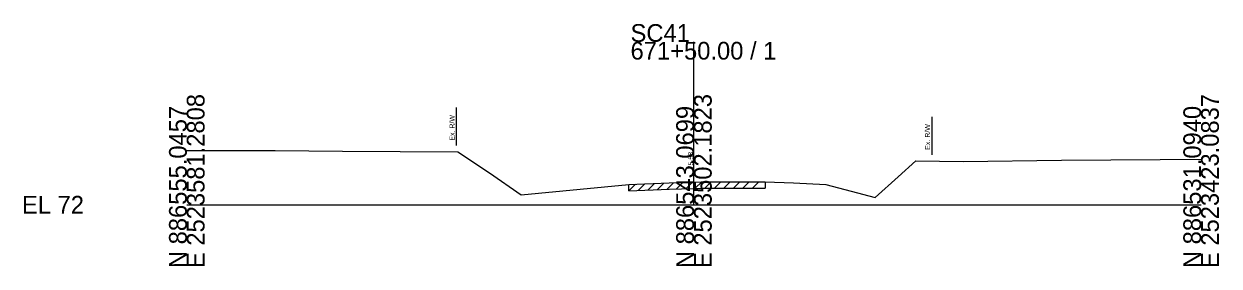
# Model space of a CAD drawing. Extents: x -26 to 183, y -10 to 24021.
# Drawn here: x -25.7 to 162.8, y 3990.3 to 4028.6 of the extents above; entities that cross this region are included whole.
import ezdxf

# ---------------------------------------------------------------- set-up
doc = ezdxf.new("R2010")
doc.units = 0
for name, color, linetype in [('RD_GPK_XS_Cell', 7, 'Continuous'), ('RD_XS_ExGround', 7, 'Continuous'), ('RD_XS_ExPaveRet', 7, 'Continuous'), ('RD_XS_ExRW', 7, 'Continuous'), ('RD_XS_TX_Elev_EX', 7, 'Continuous')]:
    doc.layers.add(name, color=color, linetype=linetype)

msp = doc.modelspace()

# ---------------------------------------------------------------- linework, layer by layer
at = {"layer": 'RD_GPK_XS_Cell'}
for p, q in [((80, 4000), (80, 4025.72)), ((0, 4000), (80, 4000)), ((80, 4000), (160, 4000))]:
    msp.add_line(p, q, dxfattribs=at)
at = {"layer": 'RD_XS_ExGround'}
for p, q in [((0, 4008.56), (2.23, 4008.57)), ((2.23, 4008.57), (13.92, 4008.56)), ((13.92, 4008.56), (24.55, 4008.48)), ((24.55, 4008.48), (42.76, 4008.33)), ((42.76, 4008.33), (47.75, 4005.03)), ((112.24, 4004.42), (115.01, 4006.93)), ((115.01, 4006.93), (122.48, 4006.83)), ((122.48, 4006.83), (138, 4007.06)), ((138, 4007.06), (153.56, 4007.15)), ((153.56, 4007.15), (160, 4007.18)), ((47.75, 4005.03), (52.77, 4001.55)), ((62.05, 4002.44), (69.72, 4003.21)), ((69.72, 4003.21), (76.1, 4003.44)), ((76.1, 4003.44), (80, 4003.58)), ((80, 4003.58), (81.14, 4003.62)), ((81.14, 4003.62), (85.47, 4003.62)), ((85.47, 4003.62), (91.26, 4003.63)), ((91.26, 4003.63), (95.7, 4003.44)), ((95.7, 4003.44), (100.8, 4003.19)), ((100.8, 4003.19), (104.78, 4002.15)), ((108.57, 4001.14), (112.24, 4004.42)), ((52.77, 4001.55), (62.05, 4002.44)), ((104.78, 4002.15), (108.57, 4001.14))]:
    msp.add_line(p, q, dxfattribs=at)
at = {"layer": 'RD_XS_ExPaveRet'}
for p, q in [((69.72, 4002.21), (70.76, 4003.25)), ((69.72, 4002.21), (69.72, 4003.21)), ((71.22, 4002.26), (72.26, 4003.3)), ((72.72, 4002.32), (73.76, 4003.35)), ((74.22, 4002.37), (75.26, 4003.41)), ((75.72, 4002.42), (76.76, 4003.46)), ((76.1, 4002.44), (80, 4002.58)), ((77.22, 4002.48), (78.26, 4003.52)), ((78.72, 4002.53), (79.76, 4003.57)), ((80, 4002.58), (81.14, 4002.62)), ((80.22, 4002.59), (81.26, 4003.62)), ((81.14, 4002.62), (85.47, 4002.62)), ((81.72, 4002.62), (82.72, 4003.62)), ((83.22, 4002.62), (84.22, 4003.62)), ((84.72, 4002.62), (85.73, 4003.62)), ((85.47, 4002.62), (91.26, 4002.63)), ((86.22, 4002.62), (87.23, 4003.62)), ((87.72, 4002.62), (88.73, 4003.63)), ((89.22, 4002.63), (90.23, 4003.63)), ((91.26, 4003.63), (91.26, 4002.63)), ((69.72, 4002.21), (76.1, 4002.44))]:
    msp.add_line(p, q, dxfattribs=at)
at = {"layer": 'RD_XS_ExRW'}
for p, q in [((42.5, 4015.33), (42.5, 4009.33)), ((117.5, 4013.89), (117.5, 4007.89))]:
    msp.add_line(p, q, dxfattribs=at)

# ---------------------------------------------------------------- texts
at = {"layer": 'RD_GPK_XS_Cell'}
for s, p in [('SC41', (70, 4025.72)), ('671+50.00 / 1', (70, 4022.92)), ('EL 72', (-26, 3998.6))]:
    msp.add_text(s, height=2.8, dxfattribs=at).set_placement(p)
for s, p in [('E 2523581.2808', (2.8, 3990)), ('E 2523502.1823', (82.8, 3990)), ('E 2523423.0837', (162.8, 3990)), ('N 886555.0457', (0, 3990)), ('N 886543.0699', (80, 3990)), ('N 886531.0940', (160, 3990))]:
    msp.add_text(s, height=2.8, rotation=90, dxfattribs=at).set_placement(p)
at = {"layer": 'RD_XS_ExRW'}
for p in [(42.25, 4010.12), (117.25, 4008.68)]:
    msp.add_text('Ex. R/W ', height=0.8, rotation=90, dxfattribs=at).set_placement(p)
at = {"layer": 'RD_XS_TX_Elev_EX'}
msp.add_text('75.58', height=0.8, rotation=90, dxfattribs=at).set_placement((79.9, 4005.58))

doc.saveas('drawing.dxf')
